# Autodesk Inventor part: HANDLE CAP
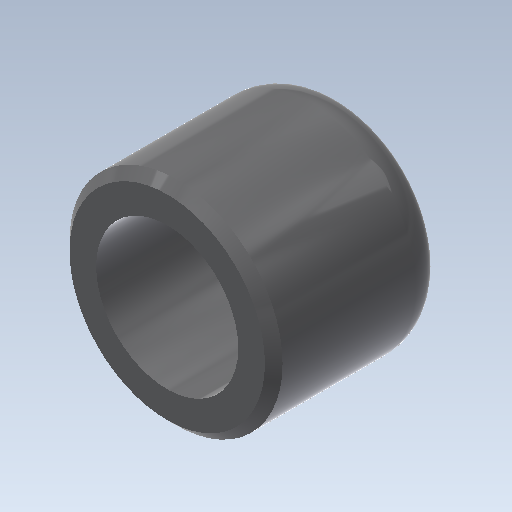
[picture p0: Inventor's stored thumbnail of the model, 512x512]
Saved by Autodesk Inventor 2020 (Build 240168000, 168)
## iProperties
Part Number: HANDLE CAP
Document SubType Name: Modeling
Created: 2003-11
Designer: Autodesk, Inc.
Manufacturer: Standard
Standards Organization: Custom
Mass: 2.20956 g
Surface Area: 17.857 cm^2
Volume: 2.37587 cm^3
Density: 0.93 g/cm^3
Material: Rubber
Appearance: Smooth - Medium Gray
Control State: 0
Master: False
Checked Out: False
Shininess: 64.0
Length Units: 11272
Angle Units: 11279
Time Units: 11290
Mass Units: 11286
Length Display Precision: 3
Angle Display Precision: 2
Compacted: True
Density: 0.0
Volumn: 0.0
Area: 0.0
PropertySet Name: Model Information
Author: Autodesk, Inc.
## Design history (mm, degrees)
sketch "Sketch1"
  geometry: C1 r 9.525 at (0, 0); C2 r 6.35 at (0, 0); 1 further point
  constraints: 2 centre point, 2 coincident
  dimensions: "d0" = 19.05 diameter of C1; "d1" = 12.7 diameter of C2
extrude "Extrusion1" new body sketch "Sketch1" distance "d2" = 15.875; taper "d3" = 0 deg
chamfer "Chamfer1" distance "d5" = 0.7874; stored, may be unused: second distance "d6" = 3.175, angle "d7" = 45 deg
fillet "Fillet2" dims "d8" = 3.175
body "Solid1"
